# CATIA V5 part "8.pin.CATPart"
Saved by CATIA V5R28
Part number: Pin
Bounding box of the stored display mesh (mm): x -50 to 50, y -5 to 5, z -5 to 5
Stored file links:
  D:\Catia Cycle design\8.pin.CATPart
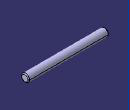
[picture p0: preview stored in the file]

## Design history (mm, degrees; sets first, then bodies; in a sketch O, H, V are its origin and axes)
Set1
  Sketch1 on yz-plane, origin (0, 0, 0), H (0, 1, 0), V (0, 0, 1)
    circle A1 centre (0, 0) radius 5
    radius A1 = 5
Body1 (main body)
  Pad1: profile Sketch1, direction (1, 0, 0), length 50, mirrored extent
  Chamfer1: length 1, angle 45, on edge [face of Pad1 from Sketch1.A1 | end face of Pad1]; edge [start face of Pad1 | face of Pad1 from Sketch1.A1]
